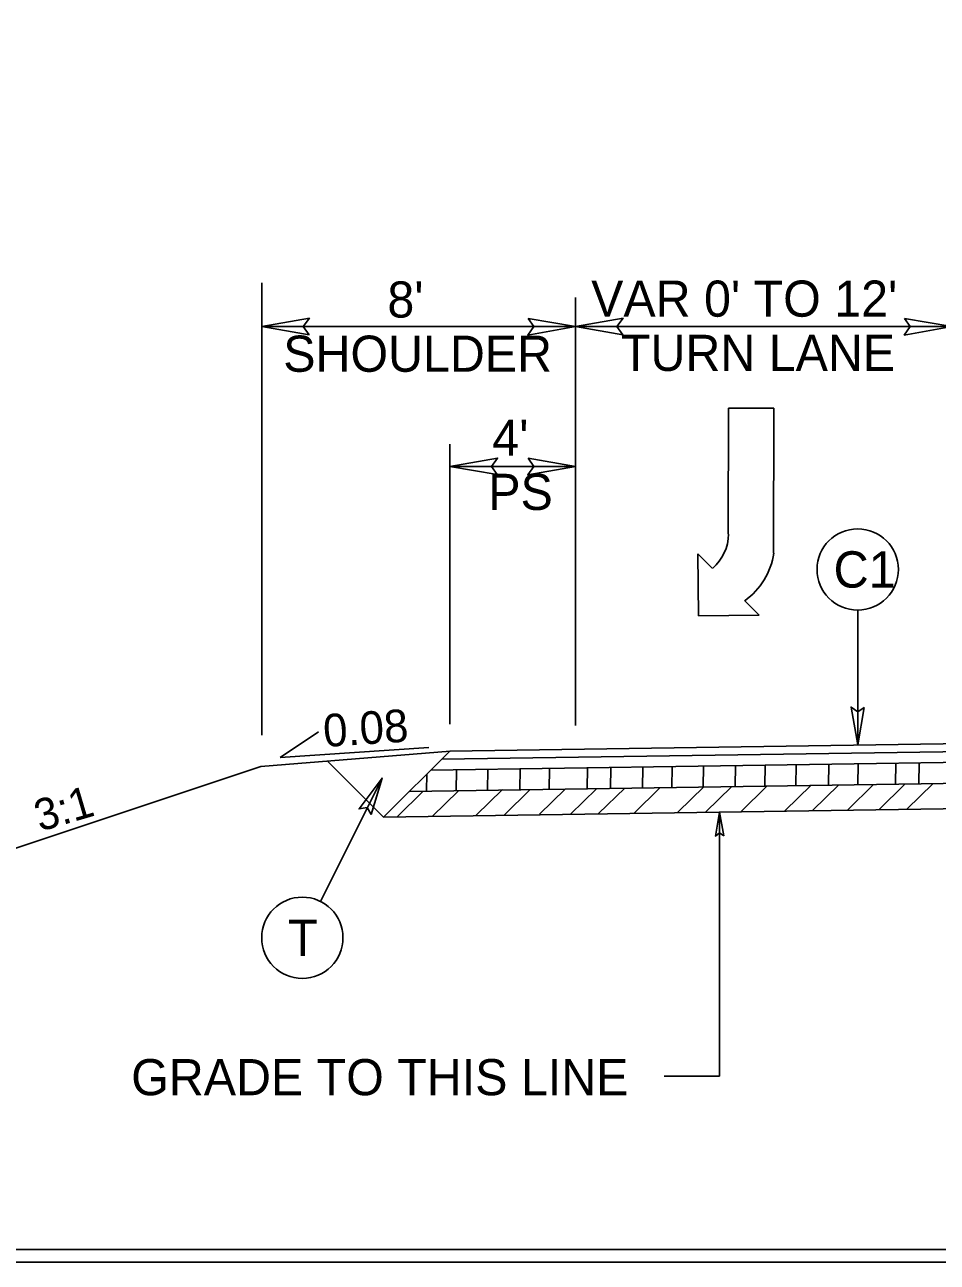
# Model space of a CAD drawing. Extents: x 2176024 to 2177225, y 75947 to 76635.
# Drawn here: x 2176725.57 to 2176754.66, y 76458.07 to 76497.55 of the extents above; entities that cross this region are included whole.
import ezdxf

# ---------------------------------------------------------------- set-up
doc = ezdxf.new("R2010")
doc.units = 0
for name, color, linetype in [('Old_Level_1', 7, 'Continuous'), ('Old_Level_11', 7, 'Continuous'), ('Prop Dimension', 7, 'Continuous'), ('Prop Lane Arrow CELL', 7, 'Continuous'), ('Sheet Plot Border Inside CELL', 7, 'Continuous'), ('Sheet Typical CELL', 7, 'Continuous'), ('Typical Curb CELL', 7, 'Continuous'), ('Typical Pavement Slope CELL', 7, 'Continuous'), ('Typical Pavement Slope Information CELL', 7, 'Continuous'), ('Typical Shoulder Slope CELL', 7, 'Continuous'), ('Typical Slope Point Local CELL', 7, 'Continuous'), ('Typical Terminator CELL', 7, 'Continuous'), ('Typical Text General CELL', 7, 'Continuous')]:
    doc.layers.add(name, color=color, linetype=linetype)

msp = doc.modelspace()

# ---------------------------------------------------------------- linework, layer by layer
at = {"layer": 'Old_Level_1'}
for p, q in [((2176754.077, 76473.327), (2176754.087, 76473.997)), ((2176738.386, 76473.101), (2176738.389, 76473.634)), ((2176739.326, 76473.108), (2176739.336, 76473.777)), ((2176740.323, 76473.132), (2176740.333, 76473.792)), ((2176741.356, 76473.145), (2176741.366, 76473.808)), ((2176742.297, 76473.152), (2176742.306, 76473.822)), ((2176743.505, 76473.168), (2176743.515, 76473.84)), ((2176744.248, 76473.181), (2176744.258, 76473.851)), ((2176745.266, 76473.194), (2176745.276, 76473.866)), ((2176746.207, 76473.202), (2176746.216, 76473.88)), ((2176747.204, 76473.226), (2176747.214, 76473.895)), ((2176748.224, 76473.247), (2176748.233, 76473.91)), ((2176749.164, 76473.254), (2176749.174, 76473.924)), ((2176750.161, 76473.278), (2176750.171, 76473.939)), ((2176751.194, 76473.291), (2176751.204, 76473.954)), ((2176752.135, 76473.298), (2176752.144, 76473.968)), ((2176753.334, 76473.314), (2176753.343, 76473.986)), ((2176746.395, 76472.422), (2176747.23, 76473.241)), ((2176747.281, 76472.428), (2176748.117, 76473.247)), ((2176748.4, 76472.432), (2176749.236, 76473.25)), ((2176749.808, 76472.473), (2176750.644, 76473.291)), ((2176750.693, 76472.476), (2176751.529, 76473.295)), ((2176751.813, 76472.505), (2176752.628, 76473.304)), ((2176752.803, 76472.505), (2176753.63, 76473.316)), ((2176753.696, 76472.524), (2176754.532, 76473.343)), ((2176737.443, 76472.281), (2176738.279, 76473.1)), ((2176738.562, 76472.285), (2176739.398, 76473.104)), ((2176739.97, 76472.326), (2176740.806, 76473.145)), ((2176740.855, 76472.33), (2176741.691, 76473.149)), ((2176741.985, 76472.359), (2176742.799, 76473.157)), ((2176742.974, 76472.359), (2176743.801, 76473.169)), ((2176743.868, 76472.378), (2176744.703, 76473.196)), ((2176744.987, 76472.381), (2176745.822, 76473.2))]:
    msp.add_line(p, q, dxfattribs=at)
at = {"layer": 'Old_Level_11'}
for p, q in [((2176752.129, 76478.872), (2176752.129, 76474.569)), ((2176735.002, 76469.578), (2176736.965, 76473.514))]:
    msp.add_line(p, q, dxfattribs=at)
for points in [[(2176752.336, 76475.769), (2176752.129, 76474.569), (2176751.916, 76475.776), (2176752.129, 76475.622)], [(2176736.614, 76472.348), (2176736.965, 76473.514), (2176736.235, 76472.53), (2176736.494, 76472.572)]]:
    msp.add_lwpolyline(points, close=True, dxfattribs=at)
for centre in [(2176752.129, 76480.168), (2176734.423, 76468.418)]:
    msp.add_circle(centre, 1.296, dxfattribs=at)
at = {"layer": 'Prop Dimension'}
for p, q in [((2176733.129, 76474.882), (2176733.129, 76489.312)), ((2176743.129, 76475.194), (2176743.129, 76488.844)), ((2176743.129, 76487.916), (2176733.129, 76487.916)), ((2176755.129, 76487.916), (2176743.235, 76487.916)), ((2176739.129, 76475.232), (2176739.129, 76484.165)), ((2176743.129, 76483.456), (2176739.129, 76483.456)), ((2176747.727, 76472.424), (2176747.727, 76463.999)), ((2176745.96, 76463.999), (2176747.727, 76463.999))]:
    msp.add_line(p, q, dxfattribs=at)
at = {"layer": 'Prop Lane Arrow CELL'}
for p, q in [((2176748.001, 76481.302), (2176748.008, 76485.317)), ((2176748.008, 76485.317), (2176749.456, 76485.314)), ((2176749.456, 76485.314), (2176749.447, 76480.685)), ((2176747.052, 76478.693), (2176747.034, 76480.668)), ((2176747.034, 76480.668), (2176747.494, 76480.206)), ((2176748.523, 76479.173), (2176748.983, 76478.711)), ((2176748.983, 76478.711), (2176747.052, 76478.693))]:
    msp.add_line(p, q, dxfattribs=at)
for centre, radius, start, end in [((2176746.571, 76481.3), 1.437, 310.2355, 359.8937), ((2176747.177, 76481.037), 2.305, 305.9059, 351.2176)]:
    msp.add_arc(centre, radius, start, end, dxfattribs=at)
at = {"layer": 'Sheet Plot Border Inside CELL'}
msp.add_lwpolyline([(2176897.987, 76626.883), (2176631.347, 76626.883), (2176631.347, 76458.067), (2176897.987, 76458.067)], close=True, dxfattribs=at)
at = {"layer": 'Sheet Typical CELL'}
msp.add_lwpolyline([(2176895.987, 76626.475), (2176655.987, 76626.475), (2176655.987, 76458.475), (2176895.987, 76458.475)], close=True, dxfattribs=at)
at = {"layer": 'Typical Curb CELL'}
for q in [(2176735.221, 76474.057), (2176762.74, 76472.648)]:
    msp.add_line((2176737.013, 76472.265), q, dxfattribs=at)
at = {"layer": 'Typical Pavement Slope CELL'}
for p, q in [((2176739.129, 76474.37), (2176737.013, 76472.265)), ((2176762.74, 76474.126), (2176738.521, 76473.765)), ((2176762.728, 76473.454), (2176737.836, 76473.084))]:
    msp.add_line(p, q, dxfattribs=at)
at = {"layer": 'Typical Pavement Slope Information CELL'}
for q in [(2176734.936, 76474.992), (2176738.458, 76474.486)]:
    msp.add_line((2176733.712, 76474.172), q, dxfattribs=at)
at = {"layer": 'Typical Shoulder Slope CELL'}
for p in [(2176739.134, 76474.37), (2176724.149, 76470.904)]:
    msp.add_line(p, (2176733.098, 76473.887), dxfattribs=at)
at = {"layer": 'Typical Slope Point Local CELL'}
for p, q in [((2176769.659, 76474.823), (2176739.129, 76474.37)), ((2176768.938, 76474.812), (2176739.129, 76474.37)), ((2176768.987, 76474.563), (2176738.874, 76474.116)), ((2176738.521, 76473.765), (2176762.74, 76474.126)), ((2176738.874, 76474.116), (2176738.521, 76473.765)), ((2176739.129, 76474.37), (2176738.874, 76474.116))]:
    msp.add_line(p, q, dxfattribs=at)
at = {"layer": 'Typical Terminator CELL'}
for points in [[(2176734.639, 76487.656), (2176733.129, 76487.916), (2176734.647, 76488.184), (2176734.454, 76487.916)], [(2176741.619, 76488.176), (2176743.129, 76487.916), (2176741.611, 76487.648), (2176741.804, 76487.916)], [(2176744.639, 76487.656), (2176743.129, 76487.916), (2176744.647, 76488.184), (2176744.454, 76487.916)], [(2176753.619, 76488.176), (2176755.129, 76487.916), (2176753.611, 76487.648), (2176753.804, 76487.916)], [(2176740.639, 76483.196), (2176739.129, 76483.456), (2176740.647, 76483.724), (2176740.454, 76483.456)], [(2176741.619, 76483.716), (2176743.129, 76483.456), (2176741.611, 76483.187), (2176741.804, 76483.456)], [(2176747.857, 76471.67), (2176747.727, 76472.424), (2176747.593, 76471.665), (2176747.727, 76471.762)]]:
    msp.add_lwpolyline(points, close=True, dxfattribs=at)

# ---------------------------------------------------------------- texts
at = {"layer": 'Old_Level_11'}
for s, rotation, p in [('C1', 0.0003, (2176751.36, 76479.588)), ('T', 359.9997, (2176733.967, 76467.838))]:
    msp.add_text(s, height=1.16, rotation=rotation, dxfattribs=at).set_placement(p)
at = {"layer": 'Typical Pavement Slope Information CELL'}
msp.add_text('0.08', height=1.0429, rotation=3.7801, dxfattribs=at).set_placement((2176735.122, 76474.502))
at = {"layer": 'Typical Slope Point Local CELL'}
msp.add_text('3:1', height=1.0064, rotation=16.4649, dxfattribs=at).set_placement((2176726.059, 76471.799))
at = {"layer": 'Typical Text General CELL'}
for s, height, p in [("VAR 0' TO 12'", 1.15334, (2176743.631, 76488.232)), ("8'", 1.1533, (2176737.135, 76488.205)), ('SHOULDER', 1.1533, (2176733.815, 76486.475)), ('TURN LANE', 1.1533, (2176744.581, 76486.502)), ("4' ", 1.1533, (2176740.481, 76483.797)), ('PS', 1.1533, (2176740.352, 76482.067)), ('GRADE TO THIS LINE', 1.15334, (2176728.967, 76463.395))]:
    msp.add_text(s, height=height, dxfattribs=at).set_placement(p)

doc.saveas('drawing.dxf')
